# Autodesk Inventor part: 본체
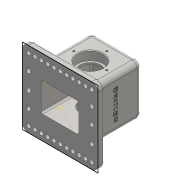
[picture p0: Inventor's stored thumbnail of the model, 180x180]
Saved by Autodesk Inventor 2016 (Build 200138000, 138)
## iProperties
Created: 2018-11
Part Number: 본체
Material: 일반
Document SubType Name: Modeling
Designer: 605-04
Density: 1 g/cm^3
Appearance: 기본값
Author: 605-04
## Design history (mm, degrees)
sketch "스케치1"
  geometry: L1 (-60, 60)-(60, 60); L2 (60, 60)-(60, -60); L3 (60, -60)-(-60, -60); L4 (-60, -60)-(-60, 60); L5 (-60, 60)-(60, -60); L6 (60, 60)-(-60, -60); 1 further point
  constraints: 12 end point, 2 midpoint, 2 parallel, 1 horizontal, 1 perpendicular
extrude "돌출1" new body sketch "스케치1" distance "d1" = 10; taper "d2" = 0 deg
sketch "스케치2"
  geometry: L1 (40, -40)-(-40, -40); L2 (-40, -40)-(-40, 40); L3 (-40, 40)-(40, 40); L4 (40, 40)-(40, -40); L5 (40, -40)-(-40, 40); L6 (-40, -40)-(40, 40); 1 further point
  constraints: 12 end point, 2 midpoint, 2 parallel, 1 horizontal, 1 perpendicular
  dimensions: "d3" = 80 distance of L2.end L3.end; "d85" = 80 distance of L1.end L2.end
extrude "돌출2" join sketch "스케치2" distance "d4" = 80; taper "d5" = 0 deg
sketch "스케치3"
  geometry: C1 r 7.5 at (0, 0); 1 further point
  constraints: 1 centre point, 1 coincident
  dimensions: "d6" = 15 diameter of C1
extrude "돌출3" join sketch "스케치3" distance "d7" = 5; taper "d8" = 0 deg
sketch "스케치4"
  geometry: 1 further point
sketch "스케치5"
  geometry: L1 (-30, -23)-(30, -23); L2 (30, -23)-(30, 23); L3 (30, 23)-(-30, 23); L4 (-30, 23)-(-30, -23); L5 (-30, -23)-(30, 23); L6 (30, -23)-(-30, 23); 1 further point
  constraints: 12 end point, 2 midpoint, 2 parallel, 1 horizontal, 1 perpendicular
  dimensions: "d9" = 46 distance of L1.end L2.end; "d26" = 60 distance of L2.end L3.end
extrude "돌출4" cut sketch "스케치5" distance "d10" = 80; taper "d11" = 0 deg
sketch "스케치6"
  geometry: L1 (100, -10)-(-20, -10) reference; C1 r 20 at (40, 38); 1 further point
  constraints: 1 centre point
  dimensions: "d12" = 48 distance from line of L1 C1.centre; "d13" = 40 diameter of C1
extrude "돌출5" cut sketch "스케치6" distance "d14" = 14; taper "d15" = 0 deg
sketch "스케치7"
  geometry: C1 r 16.5 at (0, 0); 1 further point
  constraints: 1 centre point
  dimensions: "d16" = 33 diameter of C1
extrude "돌출6" cut sketch "스케치7" distance "d17" = 3; taper "d18" = 0 deg
sketch "스케치8"
  geometry: 2 further points
  constraints: 1 coincident
hole "구멍1" sketch "스케치8" at (0, 0) diameter "d19" = 4.917; stored, may be unused: countersink angle "d23" = 90 deg, drill point angle "d25" = 118 deg; dims "d20" = 12, "d21" = 4, "d22" = 2, "d24" = 17.1
sketch "스케치9" dims "d27" = 52
  geometry: C1 r 16.5 at (40, 38) reference; 3 further points
  constraints: 1 coincident, 1 vertical alignment, 2 other
hole "구멍2" sketch "스케치9" at (40, 64) diameter "d28" = 3.242; stored, may be unused: countersink angle "d32" = 90 deg, drill point angle "d34" = 118 deg; dims "d29" = 8, "d30" = 4, "d31" = 2, "d33" = 10
chamfer "모따기1" distance "d38" = 1; stored, may be unused: second distance "d39" = 2, angle "d40" = 45 deg
fillet "모깎기1" dims "d41" = 0.6
fillet "모깎기3" dims "d43" = 8
fillet "모깎기5" dims "d61" = 10
fillet "모깎기6" dims "d62" = 3
sketch "스케치11"
  geometry: A1 r 10 centre (-50, 50) between (-50, 60) and (-60, 50) reference; A2 r 10 centre (50, 50) between (60, 50) and (50, 60) reference; A3 r 7 centre (50, -50) between (50, -57) and (57, -50) reference; A4 r 7 centre (-50, -50) between (-57, -50) and (-50, -57) reference; 17 further points
  constraints: 4 coincident
  dimensions: "d63" = 10 distance of point (-30, 50) point (-40, 50); "d64" = 10 distance of point (-20, 50) point (-30, 50); "d65" = 10 distance of point (-20, 50) point (-10, 50); "d66" = 10 distance of point (0, 50) point (-10, 50); "d67" = 10 distance of point (10, 50) point (0, 50); "d68" = 10 distance of point (20, 50) point (10, 50); "d69" = 10 distance of point (30, 50) point (20, 50); "d70" = 10 distance of point (40, 50) point (30, 50); "d71" = 25 distance of point (-50, 50) point (-50, 25); "d72" = 25 distance of point (-50, -1.665) point (-50, -26.665)
hole "구멍3" sketch "스케치11" at (-50, -50), (-50, -26.665), (-50, -1.665), (-50, 25), (-50, 50), (-40, 50), (-30, 50), (-20, 50), (-10, 50), (0, 50), (10, 50), (20, 50)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 diameter "d73" = 6.6; stored, may be unused: countersink angle "d77" = 90 deg, drill point angle "d79" = 0 deg; dims "d74" = 8, "d75" = 4, "d76" = 2, "d78" = 10
fillet "모깎기7" dims "d80" = 3
sketch "스케치12"
  geometry: L1 (82, -82)-(-18, -82) reference; 3 further points
  constraints: 1 midpoint, 1 vertical alignment, 1 other
  dimensions: "d82" = 48 distance from line of L1 point (32, -34)
feature "엠보싱1" sketch "스케치12" dims "d83" = 0.5, "d84" = 0
node "솔리드1"
mirror "대칭1"
mirror "대칭2"
pattern_circular "원형 패턴1" dims angle "d36" = 360 deg
mirror "대칭3"
mirror "대칭4"
mirror "대칭5"
